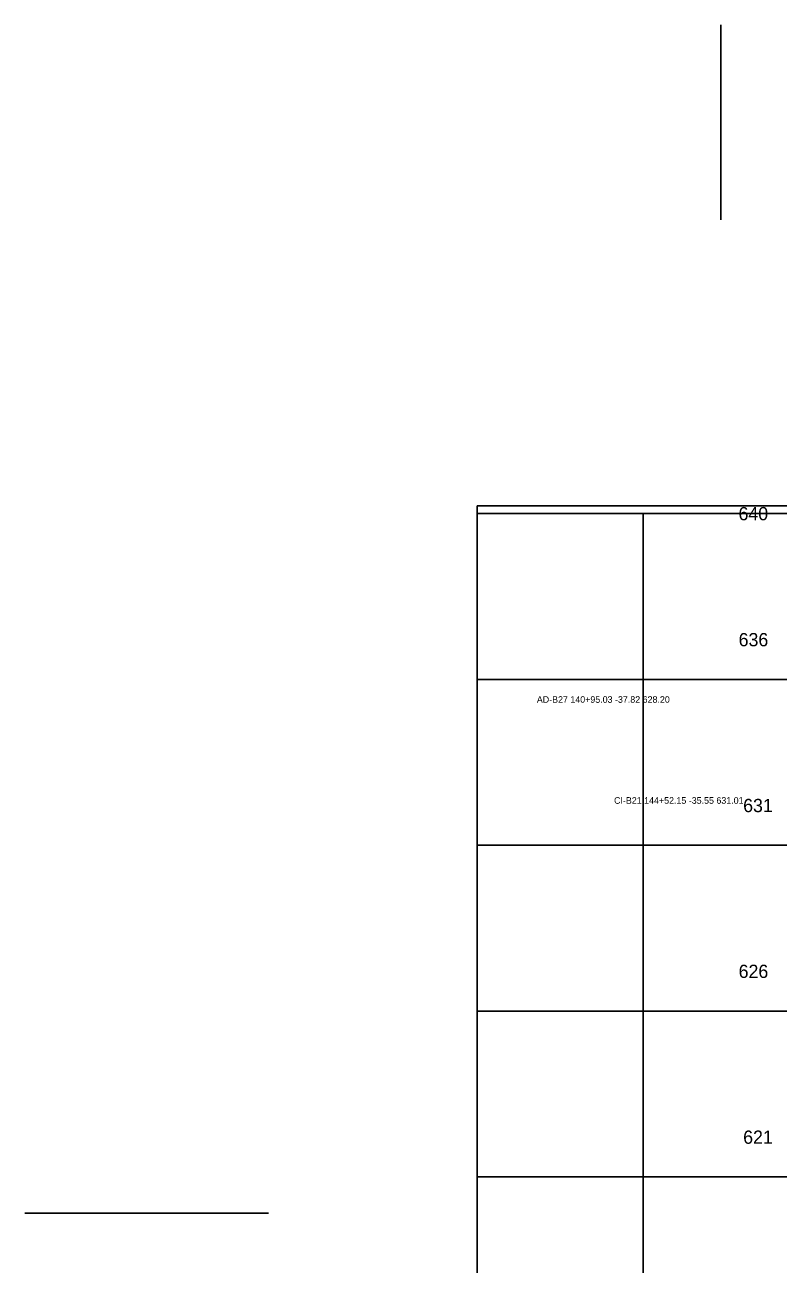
# Model space of a CAD drawing. Extents: x 2253035 to 2279930, y 13774972 to 13793443.
# Drawn here: x 2277681.2 to 2277794.8, y 13792678.1 to 13792865 of the extents above; entities that cross this region are included whole.
import ezdxf

# ---------------------------------------------------------------- set-up
doc = ezdxf.new("R2010")
doc.units = 0
for name, color, linetype in [('Default', 7, 'Continuous'), ('E_Utility_Electric_Power Pole_PP_point', 7, 'Continuous'), ('E_Utility_Telephone_Manhole Telephone_MHT_point', 7, 'Continuous'), ('E_Utility_Telephone_Telephone Pedestal_TPED_Description', 7, 'Continuous'), ('E_Utility_Water_Water Meter_WM_Description', 7, 'Continuous')]:
    doc.layers.add(name, color=color, linetype=linetype)

msp = doc.modelspace()

# ---------------------------------------------------------------- linework, layer by layer
at = {"layer": 'E_Utility_Electric_Power Pole_PP_point'}
msp.add_line((2277786.13, 13792835.56), (2277786.13, 13792864.97), dxfattribs=at)
at = {"layer": 'E_Utility_Telephone_Manhole Telephone_MHT_point'}
for p, q in [((2277749.4, 13792791.27), (2278074.4, 13792791.27)), ((2277749.4, 13792491.27), (2277749.4, 13792791.27)), ((2277774.4, 13792491.27), (2277774.4, 13792791.27)), ((2277749.4, 13792766.27), (2278074.4, 13792766.27)), ((2277749.4, 13792741.27), (2278074.4, 13792741.27)), ((2277749.4, 13792716.27), (2278074.4, 13792716.27)), ((2277749.4, 13792691.27), (2278074.4, 13792691.27))]:
    msp.add_line(p, q, dxfattribs=at)
at = {"layer": 'E_Utility_Water_Water Meter_WM_Description'}
msp.add_line((2277717.92, 13792685.82), (2277681.2, 13792685.82), dxfattribs=at)
msp.add_lwpolyline([(2278133.03, 13792792.44), (2277749.4, 13792792.44), (2277749.4, 13792491.27), (2278133.03, 13792491.27)], close=True, dxfattribs=at)

# ---------------------------------------------------------------- texts
at = {"layer": 'Default'}
for s, p in [('640', (2277788.78, 13792790.27)), ('636', (2277788.8, 13792771.27)), ('631', (2277789.48, 13792746.27)), ('626', (2277788.8, 13792721.27)), ('621', (2277789.48, 13792696.27))]:
    msp.add_text(s, height=2, dxfattribs=at).set_placement(p)
at = {"layer": 'E_Utility_Telephone_Telephone Pedestal_TPED_Description'}
for s, p in [('AD-B27 140+95.03 -37.82 628.20', (2277758.38, 13792762.75)), ('CI-B21 144+52.15 -35.55 631.01', (2277770.02, 13792747.53))]:
    msp.add_text(s, height=1, rotation=0, dxfattribs=at).set_placement(p)

doc.saveas('drawing.dxf')
